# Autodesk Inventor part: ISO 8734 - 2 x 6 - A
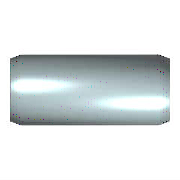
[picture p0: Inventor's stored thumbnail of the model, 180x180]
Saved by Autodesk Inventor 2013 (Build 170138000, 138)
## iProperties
Created: 2012-02
Part Number: ISO 8734 - 2 x 6 - A
Material: Stahl
Description: Zylinderstift
Document SubType Name: Modeling
Standard: ISO 8734
Designer: rYan
Standards Organization: DIN
Language: de-DE
Size Designation: 2 x 6 - A
Categories: <MemberInstance><Categories><Category DisplayName="Verbindungselemente" InternalName="e4da775c-781d-43d5-af7c-5136215cf5a6" Mnemonic="FSTN"><Category DisplayNam
Density: 7.85 g/cm^3
IsCustomPart: 0
Author: rYan
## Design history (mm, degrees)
sketch "Skizze"
  geometry: C1 r 1 at (0, 0); 1 further point
  constraints: 1 centre point, 1 coincident
  dimensions: "d1" = 2 diameter of C1 (= NND)
extrude "Körper" new body sketch "Skizze" distance "d2" = 6 (= NLG); taper "d3" = 0 deg
body "Solid1"
chamfer "Fase1" distance "d4" = 0.35 (= PHH); stored, may be unused: angle "d5" = 15 deg (= FAWI), second distance "d11" = 0.35 (= PHH)
chamfer "Fase2" distance "d8" = 0.35 (= PHH); stored, may be unused: angle "d9" = 15 deg (= FAWI), second distance "d12" = 0.35 (= PHH)
other parameters: "NND" = 2 [user parameter; used in 1 equation term], "NLG" = 6 [user parameter; used in 1 equation term], "PHH" = 0.35 [user parameter; used in 5 equation terms], "FAWI" = 15 deg [user parameter; used in 2 equation terms], "d13" = 0, "d15" = 0, "d16" = 0, "PHH2" = 0.35 (= PHH) [user parameter], "FAWI2" = 15 deg [user parameter]
